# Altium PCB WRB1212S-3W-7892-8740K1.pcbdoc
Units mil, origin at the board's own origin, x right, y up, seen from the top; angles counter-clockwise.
Board outline 933.1 x 582.7 mil, 2 copper layers (Top Layer, Bottom Layer), stack 30.8 mil thick; 26 components, 17 nets, 70 pads, 31 vias.
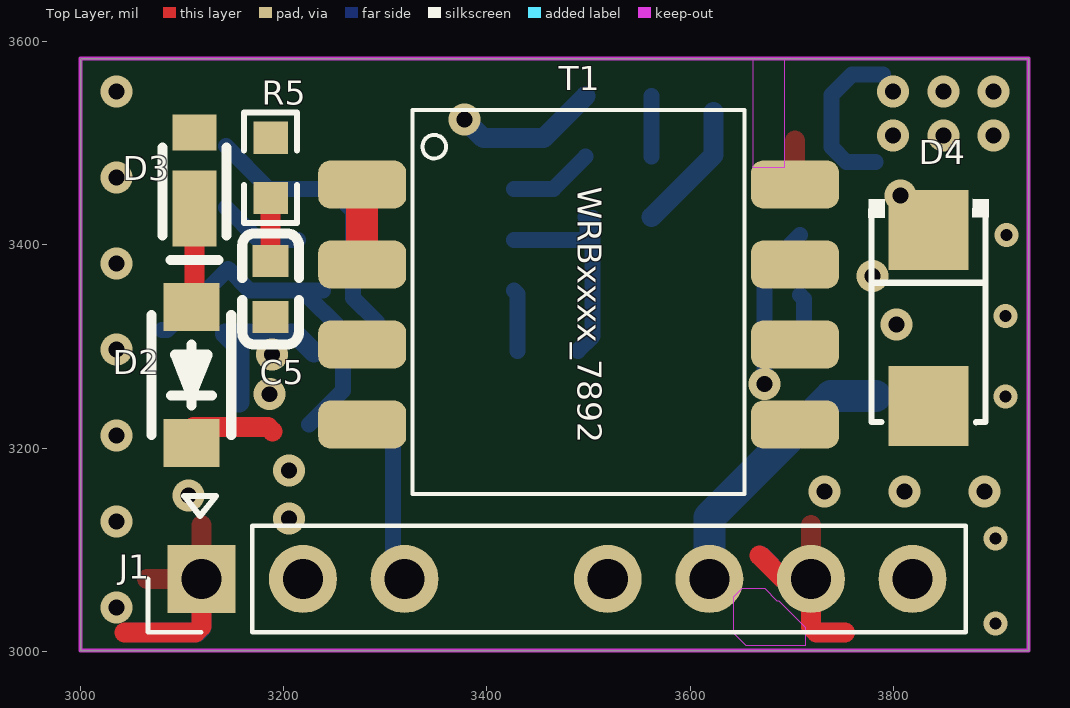
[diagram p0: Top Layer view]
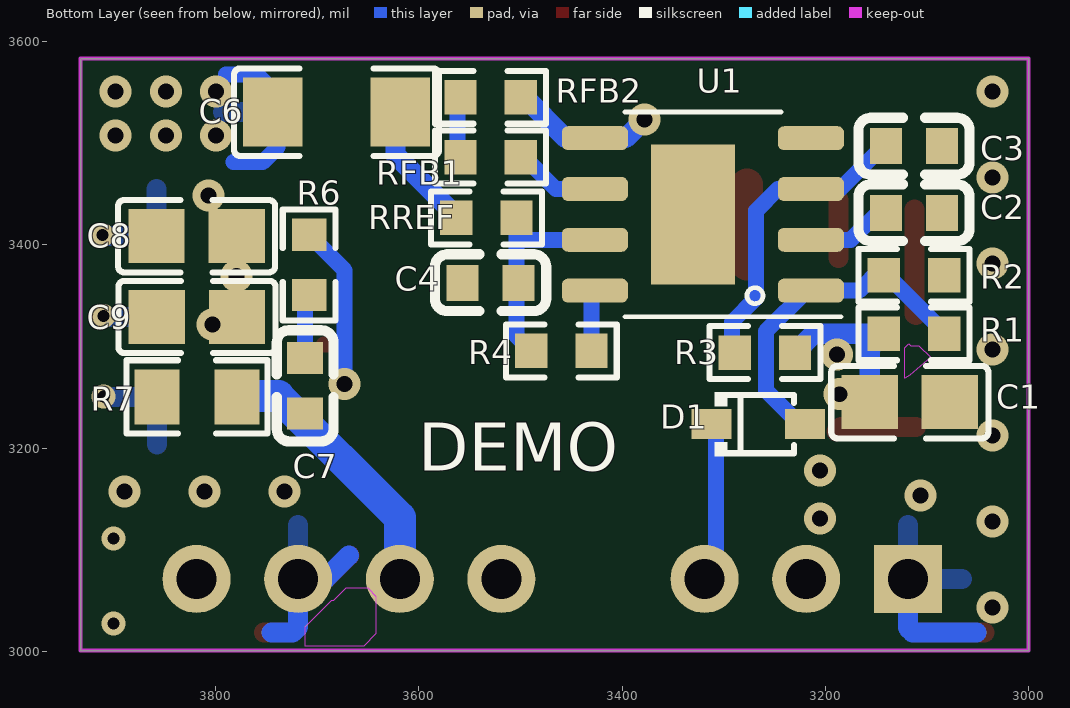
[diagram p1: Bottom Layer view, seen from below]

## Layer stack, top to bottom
Top Solder Mask Layer: solder mask 0.4, Dk 3.3
Top Layer: signal copper 1.4
Dielectric1: surface 28, FR4, Dk 4.5
Bottom Layer: signal copper 1.4
Bottom Solder Mask Layer: solder mask 0.4, Dk 3.3

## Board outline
3000,3583.5 3933.1,3583.5 3933.1,3000.8 3000,3000.8

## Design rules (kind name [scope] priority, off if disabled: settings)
BoardOutlineClearance safeClearance [All] p0: genericclearance=10 ignorepadtopadclearanceinfootprint=FALSE except(0: Arc-SplitContinuation Track-SplitContinuation SMDPad-SplitContinuation THPad-SplitContinuation Via-SplitContinuation Fill-SplitContinuation Poly-SplitContinuation Region-SplitContinuation Text-SplitContinuation)
BoardOutlineClearance Plane_innerPlane [All] p0: genericclearance=10 ignorepadtopadclearanceinfootprint=FALSE except(0: Arc-SplitContinuation Track-SplitContinuation SMDPad-SplitContinuation THPad-SplitContinuation Via-SplitContinuation Fill-SplitContinuation Poly-SplitContinuation Region-SplitContinuation Text-SplitContinuation)
BoardOutlineClearance Copper_CopperRegion [All] p0: genericclearance=10 ignorepadtopadclearanceinfootprint=FALSE except(0: Arc-SplitContinuation Track-SplitContinuation SMDPad-SplitContinuation THPad-SplitContinuation Via-SplitContinuation Fill-SplitContinuation Poly-SplitContinuation Region-SplitContinuation Text-SplitContinuation)
BoardOutlineClearance Copper_CopperRegion1 [All] p0: genericclearance=10 ignorepadtopadclearanceinfootprint=FALSE except(0: Arc-SplitContinuation Track-SplitContinuation SMDPad-SplitContinuation THPad-SplitContinuation Via-SplitContinuation Fill-SplitContinuation Poly-SplitContinuation Region-SplitContinuation Text-SplitContinuation)
BoardOutlineClearance Copper_CopperRegion2 [All] p0: genericclearance=10 ignorepadtopadclearanceinfootprint=FALSE except(0: Arc-SplitContinuation Track-SplitContinuation SMDPad-SplitContinuation THPad-SplitContinuation Via-SplitContinuation Fill-SplitContinuation Poly-SplitContinuation Region-SplitContinuation Text-SplitContinuation)
BoardOutlineClearance Copper_CopperRegion3 [All] p0: genericclearance=10 ignorepadtopadclearanceinfootprint=FALSE except(0: Arc-SplitContinuation Track-SplitContinuation SMDPad-SplitContinuation THPad-SplitContinuation Via-SplitContinuation Fill-SplitContinuation Poly-SplitContinuation Region-SplitContinuation Text-SplitContinuation)
BoardOutlineClearance Copper_CopperRegion4 [All] p0: genericclearance=10 ignorepadtopadclearanceinfootprint=FALSE except(0: Arc-SplitContinuation Track-SplitContinuation SMDPad-SplitContinuation THPad-SplitContinuation Via-SplitContinuation Fill-SplitContinuation Poly-SplitContinuation Region-SplitContinuation Text-SplitContinuation)
BoardOutlineClearance Copper_CopperRegion5 [All] p0: genericclearance=10 ignorepadtopadclearanceinfootprint=FALSE except(0: Arc-SplitContinuation Track-SplitContinuation SMDPad-SplitContinuation THPad-SplitContinuation Via-SplitContinuation Fill-SplitContinuation Poly-SplitContinuation Region-SplitContinuation Text-SplitContinuation)
BoardOutlineClearance Copper_CopperRegion6 [All] p0: genericclearance=10 ignorepadtopadclearanceinfootprint=FALSE except(0: Arc-SplitContinuation Track-SplitContinuation SMDPad-SplitContinuation THPad-SplitContinuation Via-SplitContinuation Fill-SplitContinuation Poly-SplitContinuation Region-SplitContinuation Text-SplitContinuation)
BoardOutlineClearance Copper_CopperRegion7 [All] p0: genericclearance=10 ignorepadtopadclearanceinfootprint=FALSE except(0: Arc-SplitContinuation Track-SplitContinuation SMDPad-SplitContinuation THPad-SplitContinuation Via-SplitContinuation Fill-SplitContinuation Poly-SplitContinuation Region-SplitContinuation Text-SplitContinuation)
BoardOutlineClearance Copper_CopperRegion8 [All] p0: genericclearance=10 ignorepadtopadclearanceinfootprint=FALSE except(0: Arc-SplitContinuation Track-SplitContinuation SMDPad-SplitContinuation THPad-SplitContinuation Via-SplitContinuation Fill-SplitContinuation Poly-SplitContinuation Region-SplitContinuation Text-SplitContinuation)
BoardOutlineClearance Copper_CopperRegion9 [All] p0: genericclearance=10 ignorepadtopadclearanceinfootprint=FALSE except(0: Arc-SplitContinuation Track-SplitContinuation SMDPad-SplitContinuation THPad-SplitContinuation Via-SplitContinuation Fill-SplitContinuation Poly-SplitContinuation Region-SplitContinuation Text-SplitContinuation)
BoardOutlineClearance Copper_CopperRegion10 [All] p0: genericclearance=10 ignorepadtopadclearanceinfootprint=FALSE except(0: Arc-SplitContinuation Track-SplitContinuation SMDPad-SplitContinuation THPad-SplitContinuation Via-SplitContinuation Fill-SplitContinuation Poly-SplitContinuation Region-SplitContinuation Text-SplitContinuation)
BoardOutlineClearance Copper_CopperRegion11 [All] p0: genericclearance=10 ignorepadtopadclearanceinfootprint=FALSE except(0: Arc-SplitContinuation Track-SplitContinuation SMDPad-SplitContinuation THPad-SplitContinuation Via-SplitContinuation Fill-SplitContinuation Poly-SplitContinuation Region-SplitContinuation Text-SplitContinuation)
BoardOutlineClearance Copper_CopperRegion12 [All] p0: genericclearance=10 ignorepadtopadclearanceinfootprint=FALSE except(0: Arc-SplitContinuation Track-SplitContinuation SMDPad-SplitContinuation THPad-SplitContinuation Via-SplitContinuation Fill-SplitContinuation Poly-SplitContinuation Region-SplitContinuation Text-SplitContinuation)
BoardOutlineClearance Copper_CopperRegion13 [All] p0: genericclearance=10 ignorepadtopadclearanceinfootprint=FALSE except(0: Arc-SplitContinuation Track-SplitContinuation SMDPad-SplitContinuation THPad-SplitContinuation Via-SplitContinuation Fill-SplitContinuation Poly-SplitContinuation Region-SplitContinuation Text-SplitContinuation)
BoardOutlineClearance otherClearance [All] p0: genericclearance=10 ignorepadtopadclearanceinfootprint=FALSE except(0: Arc-SplitContinuation Track-SplitContinuation SMDPad-SplitContinuation THPad-SplitContinuation Via-SplitContinuation Fill-SplitContinuation Poly-SplitContinuation Region-SplitContinuation Text-SplitContinuation)
Clearance safeClearance [All] p1: gap=7 ignorepadtopadclearanceinfootprint=FALSE
Clearance Plane_innerPlane [All] p1: gap=7 ignorepadtopadclearanceinfootprint=FALSE
Clearance Copper_CopperRegion [All] p1: gap=7 ignorepadtopadclearanceinfootprint=FALSE
Clearance Copper_CopperRegion1 [All] p1: gap=7 ignorepadtopadclearanceinfootprint=FALSE
Clearance Copper_CopperRegion2 [All] p1: gap=7 ignorepadtopadclearanceinfootprint=FALSE
Clearance Copper_CopperRegion3 [All] p1: gap=7 ignorepadtopadclearanceinfootprint=FALSE
Clearance Copper_CopperRegion4 [All] p1: gap=7 ignorepadtopadclearanceinfootprint=FALSE
Clearance Copper_CopperRegion5 [All] p1: gap=7 ignorepadtopadclearanceinfootprint=FALSE
Clearance Copper_CopperRegion6 [All] p1: gap=7 ignorepadtopadclearanceinfootprint=FALSE
Clearance Copper_CopperRegion7 [All] p1: gap=7 ignorepadtopadclearanceinfootprint=FALSE
Clearance Copper_CopperRegion8 [All] p1: gap=7 ignorepadtopadclearanceinfootprint=FALSE
Clearance Copper_CopperRegion9 [All] p1: gap=7 ignorepadtopadclearanceinfootprint=FALSE
Clearance Copper_CopperRegion10 [All] p1: gap=7 ignorepadtopadclearanceinfootprint=FALSE
Clearance Copper_CopperRegion11 [All] p1: gap=7 ignorepadtopadclearanceinfootprint=FALSE
Clearance Copper_CopperRegion12 [All] p1: gap=7 ignorepadtopadclearanceinfootprint=FALSE
Clearance Copper_CopperRegion13 [All] p1: gap=7 ignorepadtopadclearanceinfootprint=FALSE
Clearance otherClearance [All] p1: gap=7 ignorepadtopadclearanceinfootprint=FALSE
DiffPairsRouting differentialPair [All] p1: maxuncoupledlength=10 minlimit=5.9843 maxlimit=Infinity mostfreqgap=5.9843 toplayer_minwidth=5 toplayer_prefwidth=10 toplayer_maxwidth=100 bottomlayer_minwidth=5 bottomlayer_prefwidth=10 bottomlayer_maxwidth=100
PasteMaskExpansion Common [All] p1: expansion=0
PlaneConnect innerPlane [All] p1: planeconnectstyle=Relief reliefexpansion=20 reliefentries=4 reliefconductorwidth=10 reliefairgap=10
PolygonConnect CopperRegion [All] p1: connectstyle=Relief reliefentries=4 reliefconductorwidth=19.685 polygonreliefangle="90 Angle" airgapwidth=19.685
PolygonConnect CopperRegion1 [All] p1: connectstyle=Relief reliefentries=4 reliefconductorwidth=0 polygonreliefangle="90 Angle" airgapwidth=0.9843
PolygonConnect CopperRegion2 [All] p1: connectstyle=Direct reliefentries=4 reliefconductorwidth=10 polygonreliefangle="90 Angle" airgapwidth=10
PolygonConnect CopperRegion3 [All] p1: connectstyle=Relief reliefentries=4 reliefconductorwidth=19.685 polygonreliefangle="90 Angle" airgapwidth=19.685
PolygonConnect CopperRegion4 [All] p1: connectstyle=Direct reliefentries=4 reliefconductorwidth=10 polygonreliefangle="90 Angle" airgapwidth=10
PolygonConnect CopperRegion5 [All] p1: connectstyle=Direct reliefentries=4 reliefconductorwidth=10 polygonreliefangle="90 Angle" airgapwidth=10
PolygonConnect CopperRegion6 [All] p1: connectstyle=Direct reliefentries=4 reliefconductorwidth=10 polygonreliefangle="90 Angle" airgapwidth=10
PolygonConnect CopperRegion7 [All] p1: connectstyle=Direct reliefentries=4 reliefconductorwidth=10 polygonreliefangle="90 Angle" airgapwidth=10
PolygonConnect CopperRegion8 [All] p1: connectstyle=Direct reliefentries=4 reliefconductorwidth=10 polygonreliefangle="90 Angle" airgapwidth=10
PolygonConnect CopperRegion9 [All] p1: connectstyle=Relief reliefentries=4 reliefconductorwidth=19.685 polygonreliefangle="90 Angle" airgapwidth=19.685
PolygonConnect CopperRegion10 [All] p1: connectstyle=Direct reliefentries=4 reliefconductorwidth=10 polygonreliefangle="90 Angle" airgapwidth=10
PolygonConnect CopperRegion11 [All] p1: connectstyle=Relief reliefentries=4 reliefconductorwidth=19.685 polygonreliefangle="90 Angle" airgapwidth=19.685
PolygonConnect CopperRegion12 [All] p1: connectstyle=Direct reliefentries=4 reliefconductorwidth=10 polygonreliefangle="90 Angle" airgapwidth=10
PolygonConnect CopperRegion13 [All] p1: connectstyle=Direct reliefentries=4 reliefconductorwidth=10 polygonreliefangle="90 Angle" airgapwidth=10
RoutingVias viaSize [All] p1: viastyle="Through Hole" holewidth=12.0078 minholewidth=11.811 maxholewidth=236.1812 width=12.0078 minwidth=11.811 maxwidth=236.1812
SolderMaskExpansion Common [All] p1: useseparateexpansions=TRUE expansion=0 expansionbottom=0
Width trackWidth [All] p1: maxlimit=100 minlimit=5 preferedwidth=10

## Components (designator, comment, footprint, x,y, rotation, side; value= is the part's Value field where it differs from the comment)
C1 "10uF" C0805#1 3116.9,3245.3 r180 bottom
C2 "1uF" C0603#1 3112.8,3431.7 r0 bottom
C3 "1uF" C0603#1 3112.8,3497.2 r180 bottom
C4 "10pF" C0603#2 3529.5,3362.8 r180 bottom
C5 "470pF" C0603#1 3187,3356.7 r270 top
C6 "1nF" C1206 3681.1,3530.7 r180 bottom
C7 "" C0603#2 3712,3261.4 r270 bottom
C8 "22uF" C0805#2 3818.9,3408.7 r0 bottom
C9 "22uF" C0805#2 3818.5,3329.1 r0 bottom
D1 "B0540WS" SOD-323_L1.8-W1.3-LS2.5-RD 3266.1,3223.6 r180 bottom
D2 "MM1W24" SOD-123_L2.8-W1.8-LS3.9-FD 3109.1,3272 r270 top
D3 "LMBR1100ET1G" SOD-323HE_L1.9-W1.3-LS2.5-RD 3112.2,3473.2 r90 top
D4 "SS36" SMA_L4.3-W2.6-LS5.2-RD 3834.6,3328 r270 top
J1 "" ? 3118.9,3071.3 r90 top
R1 "390kΩ" R0603#1 3112.8,3312.5 r0 bottom
R2 "100kΩ" R0603#1 3112.8,3370.1 r0 bottom
R3 "0Ω" R0603#2 3259.4,3294.1 r180 bottom
R4 "NC" R0603#2 3459.8,3295.7 r180 bottom
R5 "1kΩ" R0603#2 3187,3476 r90 top
R6 "NC" R0603#3 3708.1,3380.3 r90 bottom
R7 "3.3kΩ" R0805 3818.5,3250.4 r0 bottom
RFB1 "120kΩ" R0603#2 3529.5,3486.5 r180 bottom
RFB2 "3kΩ" R0603#3 3529.5,3545.3 r0 bottom
RREF "10kΩ" R0603#3 3533.7,3426.6 r180 bottom
T1 "CMB8740K1" "coileasy:SMD-8P, 11.55x9.6, ER9.5 4+4" 3490.3,3343.7 r0 top
U1 "CMP7892" coileasy:ESOP-8 3320.5,3430.1 r0 bottom

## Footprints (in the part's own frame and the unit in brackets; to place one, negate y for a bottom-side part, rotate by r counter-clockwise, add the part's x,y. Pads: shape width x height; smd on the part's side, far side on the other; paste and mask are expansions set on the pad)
C0603#1 [mil]
  rect 31.5x35.4 smd: 1(-27.6,0) 2(27.6,0)
  silkscreen extent -55,-28 55,28
C0603#2 [mil]
  rect 31.5x35.4 smd: 1(-27.6,0) 2(27.5,0)
  silkscreen extent -55,-28 55,28
C0805#1 [mil]
  rect 55.5x53.1 smd paste-3937 mask+2: 1(-39.4,0) 2(39.3,0)
  silkscreen extent -77,-36 77,36
C0805#2 [mil]
  rect 55.5x53.1 smd paste-3937 mask+2: 1(-39.4,0) 2(39.4,0)
  silkscreen extent -77,-36 77,36
C1206 [mil]
  rect 58.5x68 smd paste-3937 mask+2: 1(-62.7,0) 2(62.7,0)
  silkscreen extent -101,-43 101,43
coileasy:ESOP-8 [mil]
  rrect50% 65x23.6 smd paste+0 mask+0: 1(-106.3,75) 2(-106.3,25) 3(-106.3,-25) 4(-106.3,-75) 5(106.3,-75) 6(106.3,-25) 7(106.3,25) 8(106.3,75)
  rect 82.7x137.8 smd paste+0 mask+0: 9(9.8,0)
  silkscreen extent -136,-101 77,101
"coileasy:SMD-8P, 11.55x9.6, ER9.5 4+4" [mil]
  rrect50% 86.6x47.2 smd paste+0 mask+0: 1(-213.1,115.7) 2(-213.1,37) 3(-213.1,-41.7) 4(-213.1,-120.5) 5(213,-120.5) 6(213,-41.7) 7(213,37) 8(213,115.7)
  silkscreen extent -163,-189 163,189
R0603#1 [mil]
  rect 31.8x34 smd paste-3937 mask+2: 1(-29.7,0) 2(29.7,0)
  silkscreen extent -54,-26 54,26
R0603#2 [mil]
  rect 31.8x34 smd paste-3937 mask+2: 1(-29.7,0) 2(29.6,0)
  silkscreen extent -55,-26 54,26
R0603#3 [mil]
  rect 31.8x34 smd paste-3937 mask+2: 1(-29.6,0) 2(29.7,0)
  silkscreen extent -54,-26 54,26
R0805 [mil]
  rect 44.6x54.2 smd paste-3937 mask+2: 1(-39.4,0) 2(39.4,0)
  silkscreen extent -69,-36 69,36
SMA_L4.3-W2.6-LS5.2-RD [mil]
  rect 78.7x78.7 smd: 1(-86.6,0) 2(86.7,0)
  silkscreen extent -117,-59 102,59
SOD-123_L2.8-W1.8-LS3.9-FD [mil]
  rect 47.2x55.1 smd: 1(-67,0) 2(66.9,0)
  silkscreen extent -59,-39 59,39
SOD-323_L1.8-W1.3-LS2.5-RD [mil]
  rect 39.4x29.5 smd: 1(-46.2,0) 2(46.1,0)
  silkscreen extent -43,-32 35,32
SOD-323HE_L1.9-W1.3-LS2.5-RD [mil]
  rect 74.8x43.3 smd: 1(-37.4,0)
  rect 35.4x43.3 smd: 2(37.5,0)
  silkscreen extent -88,-32 23,32
? [mil]
  rect 66.9x66.9 hole 39.4 paste+0 mask+0: 1(0,0)
  round 66.9 hole 39.4 paste+0 mask+0: 2(0,-100) 3(0,-200) 5(0,-400) 6(0,-500) 7(0,-600) 8(0,-700)
  silkscreen extent -52,-752 52,52

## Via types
v1: diameter 31.5, hole 15.7, Top Layer to Bottom Layer, 26 vias
v2: diameter 23.6, hole 11.8, Top Layer to Bottom Layer, 5 vias

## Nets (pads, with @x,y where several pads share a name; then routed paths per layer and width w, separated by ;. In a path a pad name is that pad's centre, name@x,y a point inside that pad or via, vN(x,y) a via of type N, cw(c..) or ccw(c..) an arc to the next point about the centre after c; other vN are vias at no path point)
$1N2: D4.2 R6.2 T1.5 T1.6 | length 173.1
  Top Layer w15.7: T1.6@3681.9,3302 T1.6@3693.5,3302
  Bottom Layer w15.7: v1(3673.1,3263) 3673.1,3375 R6.2
$1N3: D2.1 D3.1 | length 104.2
  Top Layer w19.7: D2.1@3111,3331.1 3112.2,3332.3 D3.1@3112.2,3434.8
$1N9: C5.1 R5.1 | length 57.1
  Top Layer w19.7: C5.1@3187,3387.2 R5.1@3187,3444.3
$1N15: D3.2 R5.2 RFB2.1 T1.1 T1.2 U1.5 | length 222.5
  Top Layer w31.5: T1.2 T1.1
  Bottom Layer w19.7: v1(3378,3523.6) 3396.5,3505.1 U1.5 3455.7,3505.1 RFB2.1@3497,3546.5
$1N16: C2.2 U1.2 | length 84.1
  Bottom Layer w15.7: C2.2@3143.3,3436.9 3175.1,3405.1 U1.2
$1N17: RFB1.2 U1.6 | length 83.4
  Bottom Layer w15.7: U1.6 3465.3,3455.1 RFB1.2@3497,3486.9
$1N18: C3.1 R3.1 U1.3 | length 300.6
  Bottom Layer w15.7: C3.1@3143.3,3497.2 3185.4,3455.1 U1.3 3246.7,3455.1 3268.1,3433.7 3268.1,3348 3291.9,3324.2 R3.1@3291.9,3294.1
$1N20: D1.2 R1.1 R2.2 U1.1 | length 354.7
  Bottom Layer w15.7: R1.1@3080.3,3316.1 3084.9,3316.1 3145.3,3376.5 3166.7,3355.1 U1.1 U1.1@3218.3,3355.1 ; D1.2@3224.8,3223.2 3258.5,3256.9 3258.5,3314.9 U1.1@3218.3,3355.1 ; U1.1@3238.6,3355.1 U1.1@3218.3,3355.1
$1N26: C4.2 R4.1 RREF.2 U1.7 | length 232.8
  Bottom Layer w15.7: U1.7 3498.6,3405.1 3499,3404.7 3499,3425.4 RREF.2@3497,3427.4 ; R4.1 3504,3310.2 RREF.2
$1N33: RFB1.1 RFB2.2 | length 59.6
  Bottom Layer w15.7: RFB1.1@3562,3486.9 RFB2.2@3562,3546.5
$1N478: C7.1 R6.1 | length 63.3
  Bottom Layer w15.7: R6.1 3712,3346.7 C7.1
$1N3750: R4.2 U1.8 | length 60.8
  Bottom Layer w15.7: U1.8 3430.2,3351.7 R4.2
CTRL: D1.1 J1.3 | length 157.8
  Bottom Layer w15.7: D1.1@3307.5,3223.2 3307.5,3081.5 J1.3@3318.9,3070.1
GND1: C1.2 C2.1 C3.2 C4.1 C6.2 J1.1 R2.1 RREF.1 U1.4 U1.9 | length 368.8
  Top Layer w19.7: 3043.3,3018.5 3113,3018.5 3118.9,3024.4 J1.1@3118.9,3070.1
  Bottom Layer w19.7: 3051.2,3018.5 3114.2,3018.5 3118.9,3023.3 J1.1@3118.9,3070.1 ; RREF.1@3562,3427.4 3623,3488.4 C6.2@3623,3530.7
  other v1: 3035.4,3043.3 3035.4,3128 3106.3,3153.5 3035.4,3212.6 3035.4,3297.2 3035.4,3381.9 3035.4,3466.5 3035.4,3551.2
GND2: C6.1 C8.2 C9.2 J1.7 R7.2 T1.7 T1.8 | length 438.5
  Top Layer w19.7: 3668.5,3094.5 3691.7,3071.3 J1.7 3718.9,3023.9 3724.3,3018.5 3752.5,3018.5
  Bottom Layer w15.7: 3782.7,3481.5 3753.9,3481.5 3739.2,3496.3 3739.2,3547.8 3759.1,3567.7 3789.8,3567.7
  Bottom Layer w19.7: 3668.9,3094.5 3692.1,3071.3 J1.7 3718.9,3023.9 3724.3,3018.5 3744.9,3018.5
  other v1: 3732.3,3157.5 3811,3157.5 3889.8,3157.5 3799.6,3507.9 3849.2,3507.9 3898.8,3507.9 3799.6,3551.2 3849.2,3551.2 3898.8,3551.2
  other v2: 3900.6,3027.6 3900.6,3111 3910.6,3250.7 3910.6,3330.2 3911.3,3409.6
VIN: C1.1 C5.2 D2.2 J1.2 R1.2 R3.2 T1.3 T1.4 | length 247.6
  Top Layer w19.7: D2.2@3111,3220.9 3184.6,3220.9 3189,3216.5
  Bottom Layer w20: C1.1 3156.3,3298.6 R1.2 3211.4,3312.5 R3.2
  other v1: 3205.1,3130.7 3205.1,3178 3186.2,3253.1 3188.6,3292.1
VO: C7.2 C8.1 C9.1 D4.1 J1.6 R7.1 | length 275.6
  Bottom Layer w31.5: J1.6@3618.9,3068.9 3618.9,3131.7 3738.4,3251.2 R7.1@3782.2,3251.2
  other v1: 3803,3321.9 3779.5,3369.3 3807,3448.9
pads on no net: J1.5 J1.8

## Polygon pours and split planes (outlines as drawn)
GND1 on Bottom Layer (solid, remove dead copper, pour order 26): 3289,3348.7 3289,3391.1 3371.2,3391.1 3371.2,3361.4 3371,3361.1 3371,3262.7 3518.6,3262.7 3539.4,3283.5 3539.4,3448.8 3574.1,3448.8 3578.8,3444.1 3578.8,3248.1 3559.1,3228.3 3334.8,3228.3 3328.8,3234.4 3328.8,3311 3316.9,3322.9 3314.8,3322.9
GND1 on Top Layer (solid, remove dead copper, pour order 0): 3000,3149.6 3000,3582.7 3070.9,3582.7 3070.9,3185 3074.8,3181.1 3153.5,3181.1 3153.5,3149.6
GND1 on Top Layer (solid, remove dead copper, pour order 2): 3000,3161.4 3153.5,3161.4 3153.5,3000 3000,3000
GND1 on Bottom Layer (solid, remove dead copper, pour order 16): 3000,3161.4 3153.5,3161.4 3153.5,3000 3000,3000
GND2 on Top Layer (solid, remove dead copper, pour order 4): 3748,3358.3 3748,3474 3771.7,3474 3771.7,3574.8 3661.4,3574.8 3661.4,3358.3
GND2 on Bottom Layer (solid, remove dead copper, pour order 18): 3716.5,3473.4 3716.5,3582.7 3933.1,3582.7 3933.1,3000 3657.5,3000 3657.5,3196.9 3837.6,3196.9 3837.6,3473.4
VO on Bottom Layer (solid, remove dead copper, pour order 20): 3828.7,3221.7 3828.7,3463.8 3753.1,3463.8 3753.1,3221.7
VO on Top Layer (solid, remove dead copper, pour order 6): 3753.9,3300.4 3753.9,3463.8 3889.8,3463.8 3889.8,3300.4
$1N2 on Top Layer (solid, remove dead copper, pour order 8): 3657.5,3205.9 3657.5,3292.5 3889.8,3292.5 3889.8,3205.9
$1N15 on Top Layer (solid, remove dead copper, pour order 10): 3088.6,3540.6 3399.6,3540.6 3399.6,3489.4 3322.8,3489.4 3322.8,3434.3 3252,3434.3 3252,3491.3 3088.6,3491.3
GND2 on Top Layer (solid, remove dead copper, pour order 12): 3661.4,3367.3 3661.4,3581.9 3933.1,3581.9 3933.1,3000 3657.5,3000
GND1 on Bottom Layer (solid, remove dead copper, pour order 22): 3153.5,3149.6 3153.5,3492.1 3244.1,3492.1 3271.7,3464.6 3354.3,3464.6 3358.3,3468.5 3358.3,3582.7 3000,3582.7 3000,3149.6
VIN on Bottom Layer (solid, remove dead copper, pour order 24): 3165.4,3003.9 3165.4,3208.7 3129.9,3208.7 3129.9,3330.7 3133.9,3334.6 3236.2,3334.6 3252,3318.9 3252,3000 3169.3,3000
VIN on Top Layer (solid, remove dead copper, pour order 14): 3252,3000 3252,3189 3322.8,3189 3322.8,3326.8 3165.4,3326.8 3165.4,3000 3169.3,3000

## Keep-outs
Top Layer:
  region: 3661.4,3476.4 3692.9,3476.4 3692.9,3582.7 3661.4,3582.7
  region: 3651.1,3061.9 3673.2,3061.9 3685.2,3049.9 3687.2,3049.9 3713.3,3023.8 3713.3,3005.7 3655.1,3005.7 3643,3017.7 3643,3053.9
Bottom Layer:
  region: 3107.9,3300.8 3096.4,3289.3 3117.1,3272 3122,3268.7 3122,3298.8 3118,3302.9 3116,3300.8
  region: 3650.1,3061.9 3672.2,3061.9 3684.2,3049.9 3686.2,3049.9 3712.3,3023.8 3712.3,3005.7 3654.1,3005.7 3642,3017.7 3642,3053.9
Board Outline Layer:
  the board outline again, w3.9

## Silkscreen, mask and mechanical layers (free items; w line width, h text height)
Top Silkscreen Layer:
  lines w5.9: 3102,3152.9 3133.5,3152.9 3117.7,3133.2 3102,3152.9
  text "WRBxxxx_7892" at 3489.4,3457.5 h23.6 r270
Bottom Silkscreen Layer:
  text "DEMO" at 3600.8,3177.6 h47.2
